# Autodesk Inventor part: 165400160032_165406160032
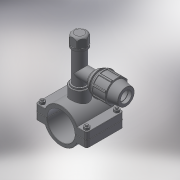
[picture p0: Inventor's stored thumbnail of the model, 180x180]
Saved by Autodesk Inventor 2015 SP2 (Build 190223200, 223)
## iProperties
Created: 2017-05
Part Number: 165400160032_165406160032
Material: Generic
Description: PLASSON TAPPER FOR PE+PVC PIPE 160-32
Document SubType Name: Modeling
Designer: KIM
Density: 1 g/cm^3
Appearance: Default
Author: KIM
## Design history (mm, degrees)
derived "16540.ipt"
feature "Solid1::16540.ipt"
feature "Solid2::16540.ipt"
tag "TaggingFeature1"
body "Solid1"
other parameters: "d0" = 176, "d1" = 223, "d4" = 145, "d5" = 0, "d6" = 11.15, "d7" = 223, "d8" = 0.1, "d10" = 0, "d11" = 1.6, "d14" = 50.6376, "d20" = 1.6, "d23" = 1.6, "d36" = 15, "d37" = 12, "d38" = 88, "d39" = 0, "d40" = 3, "d41" = 5, "d42" = 0, "d44" = 3, "d45" = 0, "d46" = 1.6, "d51" = 117, "d52" = 38.952, "d53" = 25, "d54" = 0, "d55" = 32, "d57" = 0, "d58" = 172.8, "d60" = 0, "d62" = 15, "d63" = 12, "d66" = 121, "d67" = 32, "d68" = 9.08333, "d69" = 21.8, "d70" = 64, "d71" = 48, "d72" = 1.55714, "d73" = 51.2, "d74" = 120 deg, "d75" = 48, "d76" = 10 deg, "d77" = 57.6, "d78" = 32.7, "d79" = 71, "d80" = 25.6, "d81" = 109, "d82" = 7.1, "d87" = 15.57143, "d90" = 59.52, "d91" = 35 deg, "d92" = 17.5 deg, "d94" = 0, "d96" = 360 deg, "d98" = 0.64, "d99" = 78.1, "d100" = 35.0568, "d101" = 135 deg, "d102" = 1.28, "d105" = 3.2, "d106" = 0, "d107" = 0.1, "d108" = 35.0568, "d109" = 42.8472, "d111" = 26.4, "d112" = 6.6, "d113" = 3.63333, "d116" = 0, "d117" = 38, "d118" = 21.8, "d119" = 0, "d121" = 132, "d122" = 59, "B_" = 32, "G_" = 38.952, "A_" = 117, "L_" = 223, "L_1" = 145, "l_2" = 25, "d_1" = 32, "E_" = 64, "l_" = 71, "H_" = 109, "H_1" = 59, "H_2" = 132
